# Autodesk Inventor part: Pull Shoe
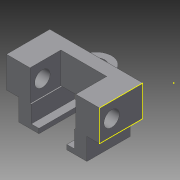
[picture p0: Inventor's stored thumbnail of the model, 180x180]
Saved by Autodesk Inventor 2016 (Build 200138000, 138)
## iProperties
Created: 2013-11
Part Number: Pull Shoe
Material: Generic
Document SubType Name: Modeling
Designer: 603839
Density: 1 g/cm^3
Appearance: Default
Mass: 5.74904 g
Surface Area: 34.2005 cm^2
Volume: 5.74904 cm^3
Author: 603839
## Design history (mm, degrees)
sketch "Sketch1"
  geometry: L1 (-19.05, -6.35)-(19.05, -6.35); L2 (19.05, -6.35)-(19.05, 6.35); L3 (19.05, 6.35)-(-19.05, 6.35); L4 (-19.05, 6.35)-(-19.05, -6.35); L5 (-19.05, -6.35)-(19.05, 6.35); L6 (19.05, -6.35)-(-19.05, 6.35); 1 further point
  constraints: 12 end point, 2 midpoint, 2 parallel, 1 horizontal, 1 perpendicular
  dimensions: "d0" = 38.1 distance of L1.start L1.end; "d1" = 12.7 distance of L2.end L1.end
extrude "Extrusion1" new body sketch "Sketch1" distance "d2" = 25.4; taper "d3" = 0 deg
sketch "Sketch6"
  geometry: L1 (38.1, 0)-(38.1, -25.4) reference; L2 (38.1, 0)-(0, 0) reference; L3 (0, 0)-(0, -25.4) reference; A1 r 20.637 centre (19.05, -20.637) between (38.1, -12.7) and (0, -12.7); 1 further point
  constraints: 3 point on circle, 2 midpoint, 1 centre point
extrude "Extrusion4" cut sketch "Sketch6" distance "d15" = 25.4; taper "d16" = 0 deg
sketch "Sketch7"
  geometry: C1 r 3.175 at (19.05, 25.4); C2 r 5.08 at (19.05, 25.4); 1 further point
  constraints: 2 centre point, 2 coincident
  dimensions: "d17" = 6.35 diameter of C1; "d18" = 10.16 diameter of C2
extrude "Extrusion5" join sketch "Sketch7" distance "d19" = 12.7; taper "d20" = 0 deg
sketch "Sketch8"
  geometry: A1 r 20.637 centre (19.05, 4.763) between (14.009, 24.775) and (0, 12.7) reference; A2 r 20.637 centre (19.05, 4.763) between (38.1, 12.7) and (24.091, 24.775) reference; A3 r 5.08 centre (19.05, 25.4) between (24.091, 24.775) and (14.009, 24.775) reference; A4 r 3.175 centre (19.05, 25.4) between (22.216, 25.156) and (15.884, 25.156) reference; A5 r 20.637 centre (19.05, 4.763) between (22.216, 25.156) and (15.884, 25.156) reference; A6 r 3.175 centre (19.05, 25.4) between (22.216, 25.156) and (15.884, 25.156); A7 r 5.08 centre (19.05, 25.4) between (24.091, 24.775) and (14.009, 24.775); A8 r 20.637 centre (19.05, 4.763) between (24.091, 24.775) and (14.009, 24.775)
  constraints: 13 point on circle, 3 centre point, 3 concentric, 2 coincident
extrude "Extrusion6" cut sketch "Sketch8" distance "d21" = 6.35; taper "d22" = 0 deg
sketch "Sketch13"
  geometry: L1 (18.796, -23.136)-(18.796, 0) reference; L2 (0, 0)-(18.796, 0); L3 (18.796, 0)-(18.796, -7.62); L4 (18.796, -7.62)-(0, -7.62); L5 (0, -7.62)-(0, 0); 1 further point
  constraints: 8 end point, 2 parallel, 1 horizontal, 1 perpendicular, 1 point on line
  dimensions: "d29" = 7.62 distance of L2.end L3.end
extrude "Extrusion10" cut sketch "Sketch13" stored distance "d30" = 2.54; taper "d31" = 0 deg
sketch "Sketch18"
  geometry: L1 (-9.398, -4.763)-(-19.05, -4.763) reference; L2 (-19.05, 7.937)-(19.05, 7.937); A1 r 20.637 centre (0, 0) between (19.05, 7.937) and (-19.05, 7.937) reference; A2 r 20.637 centre (0, 0) between (19.05, 7.937) and (-19.05, 7.937); 1 further point
  constraints: 3 point on circle, 2 end point, 1 centre point, 1 concentric, 1 parallel
extrude "Extrusion13" cut sketch "Sketch18" stored distance "d47" = 2.54; taper "d49" = 0 deg
sketch "Sketch19"
  geometry: A1 r 3.175 centre (19.05, 25.4) between (22.216, 25.156) and (15.884, 25.156) reference; A2 r 20.637 centre (19.05, 4.763) between (24.091, 24.775) and (22.216, 25.156) reference; A3 r 5.08 centre (19.05, 25.4) between (24.091, 24.775) and (14.009, 24.775) reference; A4 r 20.637 centre (19.05, 4.763) between (15.884, 25.156) and (14.009, 24.775) reference
extrude "Extrusion14" cut sketch "Sketch19" stored distance "d50" = 0; taper "d51" = 0 deg
sketch "Sketch21"
  geometry: L1 (28.448, 5.08)-(-9.652, 5.08) reference; L2 (0, 0)-(18.796, 0) reference; C1 r 3.175 at (9.398, 5.398); A1 r 6.35 centre (9.398, 5.08) between (13.208, 0) and (5.588, 0); 1 further point
  constraints: 2 centre point, 2 point on circle, 2 point on line, 1 midpoint
  dimensions: "d52" = 12.7 diameter of A1; "d53" = 6.35 diameter of C1
extrude "Extrusion15" join sketch "Sketch21" stored distance "d54" = 2.54; taper "d55" = 0 deg
sketch "Sketch22"
  geometry: L1 (15.748, -5.08)-(28.448, -5.08) reference; L2 (6.239, -5.08)-(12.557, -5.08) reference; L3 (3.048, -5.08)-(15.748, -5.08); A1 r 6.35 centre (9.398, -5.08) between (3.048, -5.08) and (15.748, -5.08) reference; A2 r 3.175 centre (9.398, -5.398) between (6.239, -5.08) and (12.557, -5.08) reference; A3 r 3.175 centre (9.398, -5.398) between (6.239, -5.08) and (12.557, -5.08); A4 r 6.35 centre (9.398, -5.08) between (3.048, -5.08) and (15.748, -5.08); 2 further points
  constraints: 4 point on circle, 2 centre point, 2 concentric, 2 end point, 1 collinear
sketch "Sketch23"
  geometry: L1 (12.557, 5.08)-(6.239, 5.08) reference; L2 (28.448, 5.08)-(15.748, 5.08) reference; L3 (3.048, 5.08)-(15.748, 5.08); A1 r 3.175 centre (9.398, 5.398) between (12.557, 5.08) and (6.239, 5.08) reference; A2 r 6.35 centre (9.398, 5.08) between (15.748, 5.08) and (3.048, 5.08) reference; 1 further point
  constraints: 2 end point, 1 collinear
extrude "Extrusion16" cut sketch "Sketch23" distance "d56" = 3.048; taper "d57" = 0 deg
extrude "Extrusion17" cut sketch "Sketch22" distance "d58" = 3.048; taper "d59" = 0 deg
sketch "Sketch28"
  geometry: L1 (-19.05, -6.35)-(-9.398, -6.35) reference; L2 (-17.145, -6.35)-(-15.875, -6.35); L3 (-14.605, -6.35)-(-8.255, -6.35); L4 (-15.875, -6.35)-(-14.605, -6.35); L5 (-8.255, -6.35)-(-8.509, -6.35); L6 (-8.255, -6.35)-(-8.89, -6.35); L7 (-8.89, -6.35)-(-8.89, -15.24); L8 (-8.89, -15.24)-(-17.145, -15.24); L9 (-17.145, -15.24)-(-17.145, -13.335); L10 (-17.145, -13.335)-(-13.97, -13.335); L11 (-13.97, -13.335)-(-13.97, -6.35); 1 further point
  constraints: 20 end point, 2 point on line, 1 collinear
  dimensions: "d106" = 1.27 distance of L4.start L4.end; "d115" = 0.635 distance of L3.end L6.end; "d116" = 8.89 distance of L6.end L7.end; "d117" = 8.255 distance of L7.end L8.end; "d118" = 1.905 distance of L8.end L9.end; "d119" = 3.175 distance of L9.end L10.end
extrude "Extrusion27" join sketch "Sketch28" stored distance "d120" = 25.4; taper "d121" = 0 deg
sketch "Sketch29"
  geometry: L1 (-8.89, -6.35)-(-9.398, -6.35) reference; L2 (0, 14.685)-(0, -22.905); L3 (9.398, -6.35)-(9.398, 6.35); L4 (9.398, 6.35)-(19.05, 6.35); L5 (19.05, 6.35)-(19.05, -6.35); L6 (19.05, -6.35)-(13.97, -6.35); L7 (13.97, -6.35)-(13.97, -13.335); L8 (13.97, -13.335)-(17.145, -13.335); L9 (17.145, -13.335)-(17.145, -15.24); L10 (17.145, -15.24)-(8.89, -15.24); L11 (8.89, -15.24)-(8.89, -6.35); L12 (8.89, -6.35)-(9.398, -6.35); 9 further points
  constraints: 22 end point, 10 symmetric about line, 1 perpendicular
extrude "Extrusion28" join sketch "Sketch29" stored distance "d122" = 25.4; taper "d123" = 0 deg
sketch "Sketch32"
  geometry: L1 (9.398, 6.35)-(9.398, -6.35) reference; L2 (8.89, -6.35)-(9.398, -6.35) reference; L3 (8.89, -15.24)-(8.89, -6.35) reference; L4 (17.145, -15.24)-(8.89, -15.24) reference; L5 (17.145, -13.335)-(17.145, -15.24) reference; L6 (13.97, -13.335)-(17.145, -13.335) reference; L7 (13.97, -6.35)-(13.97, -13.335) reference; L8 (13.97, -6.35)-(19.05, -6.35) reference; L9 (19.05, -6.35)-(19.05, 6.35) reference; L10 (19.05, 6.35)-(9.398, 6.35) reference; 1 further point
sketch "Sketch33"
  geometry: L1 (-9.398, -6.35)-(-9.398, 6.35) reference; L2 (-9.398, 6.35)-(-19.05, 6.35) reference; L3 (-19.05, 6.35)-(-19.05, -6.35) reference; L4 (-19.05, -6.35)-(-13.97, -6.35) reference; L5 (-13.97, -6.35)-(-13.97, -13.335) reference; L6 (-13.97, -13.335)-(-17.145, -13.335) reference; L7 (-17.145, -13.335)-(-17.145, -15.24) reference; L8 (-17.145, -15.24)-(-8.89, -15.24) reference; L9 (-8.89, -15.24)-(-8.89, -6.35) reference; L10 (-8.89, -6.35)-(-9.398, -6.35) reference; 1 further point
extrude "Extrusion30" join sketch "Sketch33" distance "d126" = 5.08; taper "d127" = 0 deg
extrude "Extrusion31" join sketch "Sketch32" distance "d128" = 5.08; taper "d129" = 0 deg
sketch "Sketch34"
  geometry: L1 (0, 0)-(0, 12.7) reference; L2 (0, 12.7)-(-17.78, 12.7) reference; L3 (-17.78, 0)-(-17.78, 12.7) reference; L4 (0, 0)-(-17.78, 0) reference; 1 further point
hole "Hole2" diameter "d132" = 6.35; stored, may be unused: countersink angle "d136" = 82 deg, drill point angle "d138" = 118 deg; dims "d130" = 5.08, "d131" = 6.35, "d133" = 19.05, "d134" = 9.525, "d135" = 6.35, "d137" = 25.4
sketch "Sketch35"
  geometry: L1 (-8.89, -15.24)-(-8.89, -6.35) reference; L2 (-8.89, -6.35)-(-9.398, -6.35) reference; L3 (-8.89, -15.24)-(-5.715, -15.24); L4 (-8.89, -15.24)-(-5.715, -15.24); L5 (-5.715, -15.24)-(-5.715, -13.335); L6 (-5.715, -13.335)-(-8.89, -13.335); 1 further point
  constraints: 8 end point, 2 perpendicular, 1 collinear, 1 horizontal, 1 parallel, 1 point on line
  dimensions: "d139" = 3.175 distance of L1.start L3.end; "d140" = 0 distance between parallel lines of L4 L3 (derived)
sketch "Sketch36"
  geometry: L1 (8.89, -6.35)-(8.89, -15.24) reference; L2 (19.05, 6.35)-(9.398, 6.35) reference; L3 (8.89, -15.24)-(5.715, -15.24); L4 (5.715, -15.24)-(5.715, -13.335); L5 (5.715, -13.335)-(8.89, -13.335); 1 further point
  constraints: 6 end point, 2 perpendicular, 1 parallel, 1 point on line
  dimensions: "d141" = 3.175 distance of L1.end L3.end
extrude "Extrusion32" join sketch "Sketch35" stored distance "d142" = 5.08; taper "d143" = 0 deg
extrude "Extrusion33" join sketch "Sketch36" stored distance "d144" = 5.08; taper "d145" = 0 deg
sketch "Sketch37"
  geometry: L1 (-13.97, -13.335)-(-17.145, -13.335) reference; L2 (-17.145, -13.335)-(-17.145, -15.24) reference; L3 (-17.145, -15.24)-(-5.715, -15.24) reference; L4 (-13.97, -13.335)-(-13.97, -15.24); 1 further point
  constraints: 2 end point, 1 perpendicular, 1 point on line
extrude "Extrusion34" cut sketch "Sketch37" stored distance "d146" = 5.08; taper "d147" = 0 deg
sketch "Sketch39"
  geometry: L1 (5.715, -15.24)-(17.145, -15.24) reference; L2 (17.145, -15.24)-(17.145, -13.335) reference; L3 (17.145, -13.335)-(13.97, -13.335) reference; L4 (13.97, -13.335)-(13.97, -15.24); 1 further point
  constraints: 2 end point, 1 perpendicular, 1 point on line
extrude "Extrusion35" cut sketch "Sketch39" stored distance "d148" = 5.08; taper "d149" = 0 deg
body "Solid1"
